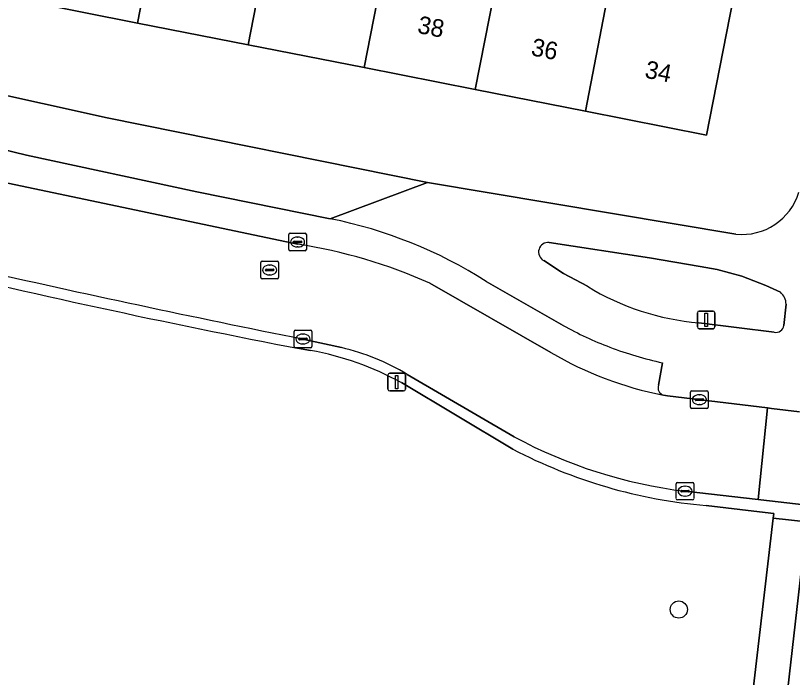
# Model space of a CAD drawing. Extents: x 161692 to 162379, y 380760 to 381678.
# Drawn here: x 162085.64 to 162129.82, y 380908.28 to 380945.92 of the extents above; entities that cross this region are included whole.
import ezdxf

# ---------------------------------------------------------------- set-up
doc = ezdxf.new("R2010")
doc.units = 0
for name, color, linetype in [('IMGEO_Boom', 7, 'Continuous'), ('IMGEO_Erf', 7, 'Continuous'), ('IMGEO_Groenvoorziening', 7, 'Continuous'), ('IMGEO_Kolk', 7, 'Continuous'), ('IMGEO_Lichtmast', 7, 'Continuous'), ('IMGEO_Pand', 7, 'Continuous'), ('IMGEO_Pand_nummerreeks', 7, 'Continuous'), ('IMGEO_Parkeervlak_open', 7, 'Continuous'), ('IMGEO_Rijbaan_lokaal_open', 7, 'Continuous'), ('IMGEO_Rioolput', 7, 'Continuous'), ('IMGEO_Voetpad_gesloten', 7, 'Continuous'), ('IMGEO_Voetpad_open', 7, 'Continuous')]:
    doc.layers.add(name, color=color, linetype=linetype)

msp = doc.modelspace()

# ---------------------------------------------------------------- linework, layer by layer
at = {"layer": 'IMGEO_Boom'}
msp.add_circle((162123.357, 380912.142), 0.489, dxfattribs=at)
at = {"layer": 'IMGEO_Erf'}
for points in [[(162126.829, 380948.799), (162124.931, 380939.129), (162118.058, 380940.482), (162111.782, 380941.717), (162105.46, 380942.962), (162098.866, 380944.26), (162092.574, 380945.498), (162086.277, 380946.738)], [(162077.47, 380943.193), (162083.472, 380941.734), (162090.856, 380940.104), (162109.076, 380936.428), (162126.605, 380933.493)]]:
    msp.add_lwpolyline(points, dxfattribs=at)
msp.add_arc((162126.955, 380936.847), 3.372, 264.049, 343.1906, dxfattribs=at)
at = {"layer": 'IMGEO_Groenvoorziening'}
for points in [[(162129.132, 380930.184), (162128.316, 380930.57), (162126.936, 380931.104), (162125.541, 380931.475), (162124.576, 380931.653), (162121.698, 380932.143), (162115.987, 380933.02)], [(162115.677, 380931.984), (162116.799, 380931.251), (162118.162, 380930.525)], [(162129.336, 380928.296), (162129.459, 380929.509)], [(162124.505, 380928.451), (162128.79, 380927.919)], [(162102.425, 380926.874), (162101.877, 380926.962)], [(162113.92, 380921.266), (162107.581, 380925.046)], [(162125.143, 380886.667), (162128.726, 380917.341), (162128.756, 380917.601), (162127.938, 380917.699), (162124.922, 380918.06)], [(162179.111, 380876.785), (162181.716, 380899.182), (162170.889, 380900.442), (162162.923, 380912.217), (162130.514, 380915.971), (162126.267, 380878.692), (162126.199, 380878.375), (162131.289, 380877.654), (162145.584, 380875.831), (162156.037, 380874.407), (162163.634, 380873.357), (162172.879, 380872.08)]]:
    msp.add_lwpolyline(points, dxfattribs=at)
for centre, radius, start, end in [((162115.938, 380932.47), 0.552, 84.8835, 241.7992), ((162197.722, 381424.116), 506.309, 256.43168, 259.08793), ((162125.675, 380942.767), 14.363, 238.4605, 265.3266), ((162128.579, 380929.499), 0.88, 0.6379, 51.0574), ((162128.893, 380928.353), 0.446, 256.6232, 352.6251), ((162099.482, 380910.387), 16.747, 61.0787, 79.8786), ((162127.386, 380946.995), 29.04, 242.3742, 265.1334)]:
    msp.add_arc(centre, radius, start, end, dxfattribs=at)
at = {"layer": 'IMGEO_Kolk'}
for p, q in [((162101.18, 380932.615), (162101.18, 380933.467)), ((162101.255, 380933.541), (162102.107, 380933.541)), ((162101.668, 380933.321), (162101.693, 380933.321)), ((162102.181, 380933.467), (162102.181, 380932.615)), ((162101.439, 380933.035), (162101.439, 380933.047)), ((162101.877, 380932.998), (162101.479, 380932.998)), ((162101.482, 380933.084), (162101.88, 380933.084)), ((162101.691, 380932.761), (162101.666, 380932.761)), ((162101.923, 380933.047), (162101.923, 380933.035)), ((162102.107, 380932.541), (162101.255, 380932.541)), ((162101.488, 380927.101), (162101.488, 380927.953)), ((162101.563, 380928.027), (162102.415, 380928.027)), ((162102.489, 380927.953), (162102.489, 380927.101)), ((162101.747, 380927.521), (162101.747, 380927.533)), ((162102.185, 380927.484), (162101.787, 380927.484)), ((162101.79, 380927.57), (162102.188, 380927.57)), ((162101.976, 380927.807), (162102.001, 380927.807)), ((162102.231, 380927.533), (162102.231, 380927.521)), ((162102.415, 380927.027), (162101.563, 380927.027)), ((162101.999, 380927.247), (162101.974, 380927.247)), ((162124.028, 380923.655), (162124.028, 380924.507)), ((162124.103, 380924.581), (162124.955, 380924.581)), ((162124.516, 380924.361), (162124.541, 380924.361)), ((162125.029, 380924.507), (162125.029, 380923.655)), ((162124.287, 380924.075), (162124.287, 380924.087)), ((162124.725, 380924.038), (162124.327, 380924.038)), ((162124.33, 380924.124), (162124.728, 380924.124)), ((162124.771, 380924.087), (162124.771, 380924.075)), ((162124.955, 380923.581), (162124.103, 380923.581)), ((162124.539, 380923.801), (162124.514, 380923.801)), ((162123.213, 380918.448), (162123.213, 380919.3)), ((162123.288, 380919.374), (162124.14, 380919.374)), ((162123.701, 380919.154), (162123.726, 380919.154)), ((162124.214, 380919.3), (162124.214, 380918.448)), ((162123.472, 380918.868), (162123.472, 380918.88)), ((162123.91, 380918.831), (162123.512, 380918.831)), ((162123.515, 380918.917), (162123.913, 380918.917)), ((162123.724, 380918.594), (162123.699, 380918.594)), ((162123.956, 380918.88), (162123.956, 380918.868)), ((162124.14, 380918.374), (162123.288, 380918.374))]:
    msp.add_line(p, q, dxfattribs=at)
for points in [[(162101.18, 380932.615), (162101.18, 380933.467)], [(162101.255, 380933.541), (162102.107, 380933.541)], [(162102.181, 380933.467), (162102.181, 380932.615)], [(162102.107, 380932.541), (162101.255, 380932.541)], [(162101.488, 380927.101), (162101.488, 380927.953)], [(162101.563, 380928.027), (162102.415, 380928.027)], [(162102.489, 380927.953), (162102.489, 380927.101)], [(162102.415, 380927.027), (162101.563, 380927.027)], [(162124.028, 380923.655), (162124.028, 380924.507)], [(162124.103, 380924.581), (162124.955, 380924.581)], [(162125.029, 380924.507), (162125.029, 380923.655)], [(162124.955, 380923.581), (162124.103, 380923.581)], [(162123.213, 380918.448), (162123.213, 380919.3)], [(162123.288, 380919.374), (162124.14, 380919.374)], [(162124.214, 380919.3), (162124.214, 380918.448)], [(162124.14, 380918.374), (162123.288, 380918.374)]]:
    msp.add_lwpolyline(points, dxfattribs=at)
for centre, radius, start, end in [((162101.257, 380933.465), 0.0765, 91.552, 178.448), ((162101.257, 380933.465), 0.0765, 91.552, 178.448), ((162102.105, 380933.465), 0.0765, 1.552, 88.448), ((162102.105, 380933.465), 0.0765, 1.552, 88.448), ((162101.479, 380933.044), 0.0403, 85.8775, 175.7526), ((162101.476, 380933.034), 0.0366, 178.938, 274.7102), ((162101.88, 380933.041), 0.043, 264.8664, 352.4533), ((162101.884, 380933.046), 0.0386, 1.7309, 96.639), ((162101.257, 380932.617), 0.0765, 181.552, 268.448), ((162101.257, 380932.617), 0.0765, 181.552, 268.448), ((162102.105, 380932.617), 0.0765, 271.552, 358.448), ((162102.105, 380932.617), 0.0765, 271.552, 358.448), ((162101.565, 380927.951), 0.0765, 91.552, 178.448), ((162101.565, 380927.951), 0.0765, 91.552, 178.448), ((162102.413, 380927.951), 0.0765, 1.552, 88.448), ((162102.413, 380927.951), 0.0765, 1.552, 88.448), ((162101.787, 380927.53), 0.0403, 85.8775, 175.7526), ((162101.784, 380927.52), 0.0366, 178.938, 274.7102), ((162102.188, 380927.527), 0.043, 264.8664, 352.4533), ((162102.192, 380927.532), 0.0386, 1.7309, 96.639), ((162101.565, 380927.103), 0.0765, 181.552, 268.448), ((162101.565, 380927.103), 0.0765, 181.552, 268.448), ((162102.413, 380927.103), 0.0765, 271.552, 358.448), ((162102.413, 380927.103), 0.0765, 271.552, 358.448), ((162124.105, 380924.505), 0.0765, 91.552, 178.448), ((162124.105, 380924.505), 0.0765, 91.552, 178.448), ((162124.953, 380924.505), 0.0765, 1.552, 88.448), ((162124.953, 380924.505), 0.0765, 1.552, 88.448), ((162124.327, 380924.084), 0.0403, 85.8775, 175.7526), ((162124.324, 380924.074), 0.0366, 178.938, 274.7102), ((162124.728, 380924.081), 0.043, 264.8664, 352.4533), ((162124.732, 380924.086), 0.0386, 1.7309, 96.639), ((162124.105, 380923.657), 0.0765, 181.552, 268.448), ((162124.105, 380923.657), 0.0765, 181.552, 268.448), ((162124.953, 380923.657), 0.0765, 271.552, 358.448), ((162124.953, 380923.657), 0.0765, 271.552, 358.448), ((162123.29, 380919.298), 0.0765, 91.552, 178.448), ((162123.29, 380919.298), 0.0765, 91.552, 178.448), ((162124.138, 380919.298), 0.0765, 1.552, 88.448), ((162124.138, 380919.298), 0.0765, 1.552, 88.448), ((162123.512, 380918.877), 0.0403, 85.8775, 175.7526), ((162123.509, 380918.867), 0.0366, 178.938, 274.7102), ((162123.913, 380918.874), 0.043, 264.8664, 352.4533), ((162123.917, 380918.879), 0.0386, 1.7309, 96.639), ((162123.29, 380918.45), 0.0765, 181.552, 268.448), ((162123.29, 380918.45), 0.0765, 181.552, 268.448), ((162124.138, 380918.45), 0.0765, 271.552, 358.448), ((162124.138, 380918.45), 0.0765, 271.552, 358.448)]:
    msp.add_arc(centre, radius, start, end, dxfattribs=at)
for centre, major_axis, ratio, start_param, end_param in [((162101.667, 380933.041), (-0.387, 0.002), 0.722429, 4.712389, 7.853982), ((162101.692, 380933.041), (-0.39, 0.002), 0.717154, 1.570796, 4.712389), ((162101.975, 380927.527), (-0.387, 0.002), 0.722429, 4.712389, 7.853982), ((162102, 380927.527), (-0.39, 0.002), 0.717154, 1.570796, 4.712389), ((162124.515, 380924.081), (-0.387, 0.002), 0.722429, 4.712389, 7.853982), ((162124.54, 380924.081), (-0.39, 0.002), 0.717154, 1.570796, 4.712389), ((162123.7, 380918.874), (-0.387, 0.002), 0.722429, 4.712389, 7.853982), ((162123.725, 380918.874), (-0.39, 0.002), 0.717154, 1.570796, 4.712389)]:
    msp.add_ellipse(centre, major_axis=major_axis, ratio=ratio, start_param=start_param, end_param=end_param, dxfattribs=at)
at = {"layer": 'IMGEO_Lichtmast'}
for p, q in [((162124.417, 380928.213), (162124.417, 380929.013)), ((162124.417, 380929.013), (162124.417, 380928.213)), ((162124.517, 380929.113), (162125.307, 380929.113)), ((162125.307, 380929.113), (162124.517, 380929.113)), ((162125.407, 380929.013), (162125.407, 380928.213)), ((162125.407, 380928.213), (162125.407, 380929.013)), ((162125.307, 380928.113), (162124.517, 380928.113)), ((162124.517, 380928.113), (162125.307, 380928.113)), ((162106.821, 380924.678), (162106.821, 380925.478)), ((162106.821, 380925.478), (162106.821, 380924.678)), ((162106.921, 380925.578), (162107.711, 380925.578)), ((162107.711, 380925.578), (162106.921, 380925.578)), ((162107.811, 380925.478), (162107.811, 380924.678)), ((162107.811, 380924.678), (162107.811, 380925.478)), ((162107.711, 380924.578), (162106.921, 380924.578)), ((162106.921, 380924.578), (162107.711, 380924.578))]:
    msp.add_line(p, q, dxfattribs=at)
for points in [[(162124.837, 380928.988), (162124.987, 380928.988), (162124.987, 380928.238), (162124.837, 380928.238), (162124.837, 380928.988)], [(162107.241, 380925.453), (162107.391, 380925.453), (162107.391, 380924.703), (162107.241, 380924.703), (162107.241, 380925.453)]]:
    msp.add_lwpolyline(points, dxfattribs=at)
for centre, start, end in [((162124.517, 380929.013), 90, 180), ((162124.517, 380929.013), 90, 180), ((162125.307, 380929.013), 0, 90), ((162125.307, 380929.013), 360, 90), ((162124.517, 380928.213), 180, 270), ((162124.517, 380928.213), 180, 270), ((162125.307, 380928.213), 270, 0), ((162125.307, 380928.213), 270, 0), ((162106.921, 380925.478), 90, 180), ((162106.921, 380925.478), 90, 180), ((162107.711, 380925.478), 0, 90), ((162107.711, 380925.478), 360, 90), ((162106.921, 380924.678), 180, 270), ((162106.921, 380924.678), 180, 270), ((162107.711, 380924.678), 270, 0), ((162107.711, 380924.678), 270, 0)]:
    msp.add_arc(centre, 0.1, start, end, dxfattribs=at)
at = {"layer": 'IMGEO_Pand'}
for points in [[(162107.647, 380954.108), (162101.052, 380955.402), (162100.51, 380952.638), (162098.866, 380944.26), (162105.46, 380942.962)], [(162087.919, 380955.109), (162086.277, 380946.738), (162092.574, 380945.498), (162094.217, 380953.873)], [(162111.782, 380941.717), (162113.426, 380950.094), (162113.309, 380950.117), (162113.853, 380952.89), (162107.647, 380954.108), (162105.46, 380942.962)], [(162100.51, 380952.638), (162094.217, 380953.873), (162092.574, 380945.498), (162098.866, 380944.26)], [(162120.281, 380952.056), (162113.934, 380953.302), (162113.853, 380952.89), (162113.309, 380950.117), (162113.426, 380950.094), (162111.782, 380941.717), (162118.058, 380940.482), (162119.656, 380948.872)], [(162126.829, 380948.799), (162126.706, 380948.823), (162127.152, 380951.095), (162124.276, 380951.66), (162124.362, 380952.097), (162121.253, 380952.707), (162121.167, 380952.27), (162120.356, 380952.439), (162120.281, 380952.056), (162119.656, 380948.872), (162118.058, 380940.482), (162124.931, 380939.129)]]:
    msp.add_lwpolyline(points, close=True, dxfattribs=at)
at = {"layer": 'IMGEO_Parkeervlak_open'}
for points in [[(162103.543, 380934.366), (162095.958, 380935.889), (162086.276, 380937.976), (162074.331, 380940.881), (162074.043, 380939.648)], [(162073.615, 380939.265), (162084.553, 380936.527), (162101.679, 380932.917)], [(162109.203, 380930.698), (162116.085, 380926.76)], [(162116.781, 380928.304), (162112.405, 380930.803)], [(162122.196, 380924.896), (162122.438, 380926.178)]]:
    msp.add_lwpolyline(points, dxfattribs=at)
for centre, radius, start, end in [((162098.47, 380908.945), 25.922, 57.4808, 78.7136), ((162097.178, 380903.792), 29.471, 65.9201, 81.216), ((162126.413, 380945.486), 19.698, 240.7251, 249.2577), ((162126.611, 380945.817), 20.078, 249.0643, 258.0037), ((162126.337, 380944.211), 20.24, 239.566, 259.0159), ((162122.616, 380924.762), 0.441, 162.293, 252.1532)]:
    msp.add_arc(centre, radius, start, end, dxfattribs=at)
at = {"layer": 'IMGEO_Rijbaan_lokaal_open'}
for points in [[(162101.679, 380932.917), (162084.553, 380936.527), (162073.615, 380939.265), (162072.471, 380939.575), (162063.01, 380942.135), (162062.2, 380942.354), (162061.904, 380942.435), (162053.339, 380944.791), (162034.3, 380950.52), (162018.278, 380956.309), (162012.438, 380958.632), (162010.753, 380953.818), (162022.315, 380949.277)], [(162116.085, 380926.76), (162109.203, 380930.698)], [(162101.989, 380927.528), (162104.181, 380927.038)], [(162107.915, 380925.514), (162113.991, 380921.971)], [(162128.402, 380923.613), (162122.712, 380924.299), (162122.481, 380924.342)], [(162123.714, 380918.875), (162127.866, 380918.397), (162128.402, 380923.613)], [(162130.212, 380923.395), (162128.632, 380923.585), (162128.402, 380923.613), (162127.866, 380918.397), (162128.018, 380918.379), (162140.168, 380916.98), (162140.919, 380916.892), (162141.468, 380922.045), (162140.247, 380922.188)]]:
    msp.add_lwpolyline(points, dxfattribs=at)
for centre, radius, start, end in [((162097.178, 380903.792), 29.471, 65.9201, 81.216), ((162248.998, 381661.519), 748.568, 257.212503, 258.674257), ((162101.211, 380914.424), 12.959, 58.8459, 76.7493), ((162126.337, 380944.211), 20.24, 239.566, 259.0159), ((162126.997, 380946.001), 27.324, 241.5759, 263.0991)]:
    msp.add_arc(centre, radius, start, end, dxfattribs=at)
at = {"layer": 'IMGEO_Rioolput'}
for p, q in [((162099.594, 380931.023), (162099.594, 380931.875)), ((162099.669, 380931.949), (162100.521, 380931.949)), ((162100.595, 380931.875), (162100.595, 380931.023)), ((162099.853, 380931.443), (162099.853, 380931.455)), ((162100.291, 380931.406), (162099.893, 380931.406)), ((162099.896, 380931.492), (162100.294, 380931.492)), ((162100.082, 380931.729), (162100.107, 380931.729)), ((162100.337, 380931.455), (162100.337, 380931.443)), ((162100.105, 380931.169), (162100.08, 380931.169)), ((162100.521, 380930.949), (162099.669, 380930.949))]:
    msp.add_line(p, q, dxfattribs=at)
for points in [[(162099.594, 380931.023), (162099.594, 380931.875)], [(162099.669, 380931.949), (162100.521, 380931.949)], [(162100.595, 380931.875), (162100.595, 380931.023)], [(162100.521, 380930.949), (162099.669, 380930.949)]]:
    msp.add_lwpolyline(points, dxfattribs=at)
for centre, radius, start, end in [((162099.671, 380931.873), 0.0765, 91.552, 178.448), ((162099.671, 380931.873), 0.0765, 91.552, 178.448), ((162100.519, 380931.873), 0.0765, 1.552, 88.448), ((162100.519, 380931.873), 0.0765, 1.552, 88.448), ((162099.893, 380931.452), 0.0403, 85.8775, 175.7526), ((162099.89, 380931.442), 0.0366, 178.938, 274.7102), ((162100.294, 380931.449), 0.043, 264.8664, 352.4533), ((162100.298, 380931.454), 0.0386, 1.7309, 96.639), ((162099.671, 380931.025), 0.0765, 181.552, 268.448), ((162099.671, 380931.025), 0.0765, 181.552, 268.448), ((162100.519, 380931.025), 0.0765, 271.552, 358.448), ((162100.519, 380931.025), 0.0765, 271.552, 358.448)]:
    msp.add_arc(centre, radius, start, end, dxfattribs=at)
for centre, major_axis, ratio, start_param, end_param in [((162100.081, 380931.449), (-0.387, 0.002), 0.722429, 4.712389, 7.853982), ((162100.106, 380931.449), (-0.39, 0.002), 0.717154, 1.570796, 4.712389)]:
    msp.add_ellipse(centre, major_axis=major_axis, ratio=ratio, start_param=start_param, end_param=end_param, dxfattribs=at)
at = {"layer": 'IMGEO_Voetpad_gesloten'}
msp.add_lwpolyline([(162124.67, 380882.601), (162124.64, 380882.344), (162124.242, 380878.904), (162126.267, 380878.692), (162130.514, 380915.971), (162130.645, 380917.122), (162128.726, 380917.341), (162125.143, 380886.667)], dxfattribs=at)
at = {"layer": 'IMGEO_Voetpad_open'}
for points in [[(162074.043, 380939.648), (162074.331, 380940.881), (162086.276, 380937.976), (162095.958, 380935.889), (162103.543, 380934.366), (162109.076, 380936.428), (162090.856, 380940.104), (162083.472, 380941.734), (162077.47, 380943.193)], [(162126.605, 380933.493), (162109.076, 380936.428), (162103.543, 380934.366)], [(162115.987, 380933.02), (162121.698, 380932.143), (162124.576, 380931.653), (162125.541, 380931.475), (162126.936, 380931.104), (162128.316, 380930.57), (162129.132, 380930.184)], [(162118.162, 380930.525), (162116.799, 380931.251), (162115.677, 380931.984)], [(162112.405, 380930.803), (162116.781, 380928.304)], [(162129.459, 380929.509), (162129.336, 380928.296)], [(162128.79, 380927.919), (162124.505, 380928.451)], [(162104.181, 380927.038), (162101.989, 380927.528)], [(162101.877, 380926.962), (162102.425, 380926.874)], [(162122.438, 380926.178), (162122.196, 380924.896)], [(162113.991, 380921.971), (162107.915, 380925.514)], [(162107.581, 380925.046), (162113.92, 380921.266)], [(162122.481, 380924.342), (162122.712, 380924.299), (162128.402, 380923.613), (162128.632, 380923.585), (162130.212, 380923.395)], [(162157.612, 380914.932), (162140.919, 380916.892), (162140.168, 380916.98), (162128.018, 380918.379), (162127.866, 380918.397), (162123.714, 380918.875)], [(162124.922, 380918.06), (162127.938, 380917.699), (162128.756, 380917.601), (162128.726, 380917.341), (162130.645, 380917.122), (162130.514, 380915.971), (162162.923, 380912.217), (162176.671, 380910.624)]]:
    msp.add_lwpolyline(points, dxfattribs=at)
for centre, radius, start, end in [((162126.955, 380936.847), 3.372, 264.049, 343.1906), ((162098.47, 380908.945), 25.922, 57.4808, 78.7136), ((162115.938, 380932.47), 0.552, 84.8835, 241.7992), ((162197.722, 381424.116), 506.309, 256.43168, 259.08793), ((162248.998, 381661.519), 748.568, 257.212503, 258.674257), ((162125.675, 380942.767), 14.363, 238.4605, 265.3266), ((162128.579, 380929.499), 0.88, 0.6379, 51.0574), ((162126.413, 380945.486), 19.698, 240.7251, 249.2577), ((162128.893, 380928.353), 0.446, 256.6232, 352.6251), ((162101.211, 380914.424), 12.959, 58.8459, 76.7493), ((162126.611, 380945.817), 20.078, 249.0643, 258.0037), ((162099.482, 380910.387), 16.747, 61.0787, 79.8786), ((162122.616, 380924.762), 0.441, 162.293, 252.1532), ((162126.997, 380946.001), 27.324, 241.5759, 263.0991), ((162127.386, 380946.995), 29.04, 242.3742, 265.1334)]:
    msp.add_arc(centre, radius, start, end, dxfattribs=at)

# ---------------------------------------------------------------- texts
at = {"layer": 'IMGEO_Pand_nummerreeks'}
for s, rotation, p in [('38', 348.8638, (162108.447, 380944.942)), ('36', 348.8617, (162114.91, 380943.67)), ('34', 348.8617, (162121.375, 380942.398))]:
    msp.add_text(s, height=1, rotation=rotation, dxfattribs=at).set_placement(p)

doc.saveas('drawing.dxf')
